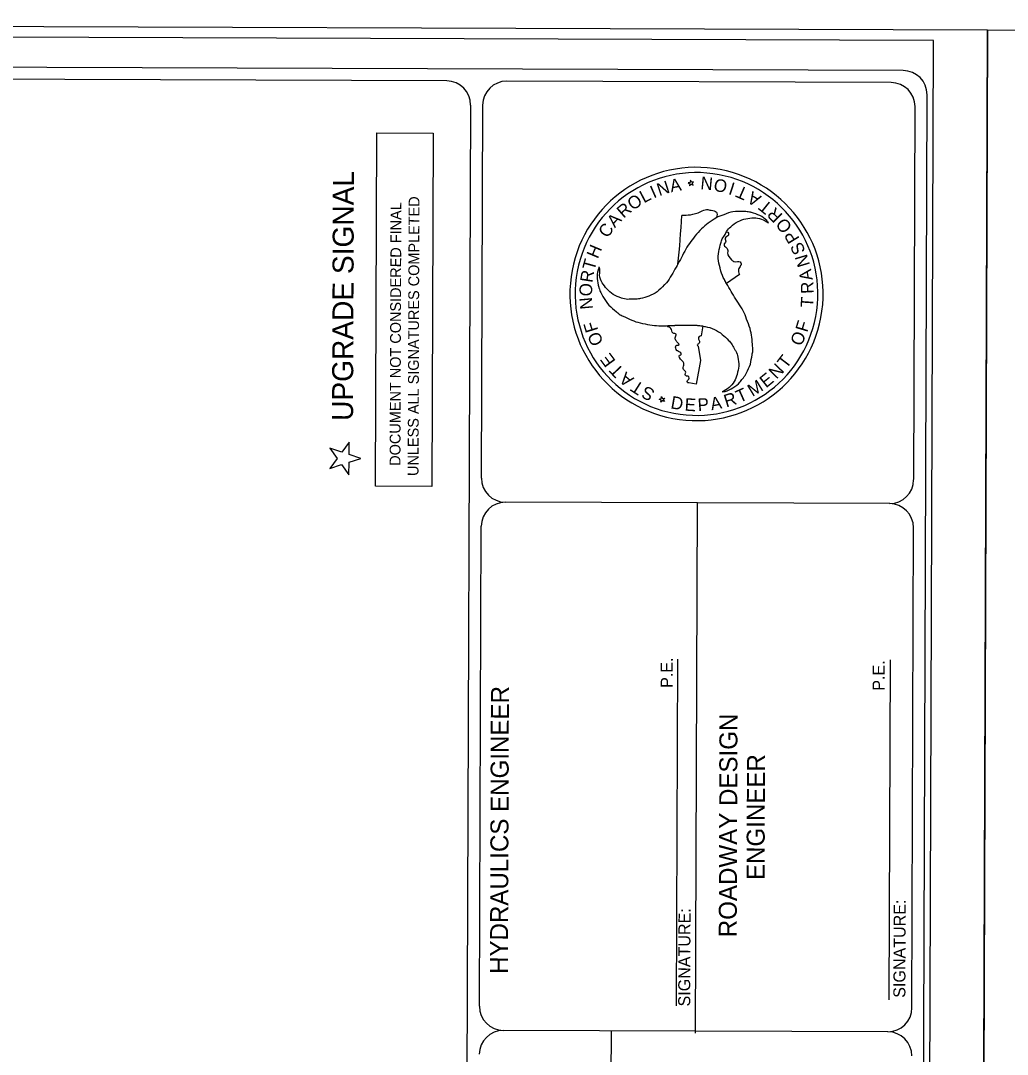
# Model space of a CAD drawing. Extents: x 2364794 to 2387902, y 795230 to 810426.
# Drawn here: x 2369718 to 2372593, y 807415 to 810426 of the extents above; entities that cross this region are included whole.
import ezdxf

# ---------------------------------------------------------------- set-up
doc = ezdxf.new("R2010")
doc.units = 0
for name, color, linetype in [('Auto Dimensioning', 7, 'Continuous'), ('Mis Object Lines', 7, 'Continuous'), ('Old_Level_21', 7, 'Continuous'), ('Old_Level_22', 7, 'Continuous'), ('Old_Level_8', 7, 'Continuous'), ('Plan Sheet CELL', 7, 'Continuous'), ('Sub End Bent Cap Lines CELL', 7, 'Continuous')]:
    doc.layers.add(name, color=color, linetype=linetype)

msp = doc.modelspace()

# ---------------------------------------------------------------- linework, layer by layer
at = {"layer": 'Auto Dimensioning'}
for p, q in [((2370751.7, 809070.1), (2370755.4, 810099.1)), ((2370755.5, 810099.1), (2370920, 810098.5)), ((2370919.9, 810098.5), (2370916.2, 809069.5)), ((2370916.2, 809069.5), (2370751.7, 809070.1))]:
    msp.add_line(p, q, dxfattribs=at)
at = {"layer": 'Mis Object Lines'}
for p, q in [((2370994.2, 800240.4), (2371029.3, 810180.3)), ((2371060.4, 809093.6), (2371064.3, 810180.2)), ((2371737.1, 809995.7), (2371737.1, 809995.7)), ((2371668.6, 809955.2), (2371662.4, 809953.8)), ((2371662.4, 809953.8), (2371668, 809951.1)), ((2371669.2, 809961.4), (2371668.6, 809955.2)), ((2371672.4, 809955.8), (2371669.2, 809961.4)), ((2371678.7, 809956.8), (2371672.4, 809955.8)), ((2371674.4, 809952.2), (2371678.7, 809956.8)), ((2371677.4, 809946.8), (2371674.4, 809952.2)), ((2371668, 809951.1), (2371667.2, 809944.8)), ((2371667.2, 809944.8), (2371671.6, 809949.5)), ((2371671.6, 809949.5), (2371677.4, 809946.8)), ((2371632.7, 809716.9), (2371632.7, 809716.9)), ((2371402.8, 809708.5), (2371403.5, 809707.7)), ((2371402.8, 809708.5), (2371403.5, 809707.7)), ((2371812.1, 809687.1), (2371774.7, 809661)), ((2371774.7, 809661), (2371774.7, 809661)), ((2371705.2, 809537), (2371700.9, 809508.1)), ((2371692.2, 809478.2), (2371698.4, 809436.8)), ((2371698.4, 809436.8), (2371686.4, 809367.8)), ((2371686.4, 809367.8), (2371664.5, 809371.6)), ((2371578.4, 809323.5), (2371584.6, 809324.8)), ((2371584, 809320.9), (2371578.4, 809323.5)), ((2371583.2, 809314.6), (2371584, 809320.9)), ((2371587.6, 809319.1), (2371583.2, 809314.6)), ((2371584.6, 809324.8), (2371585.4, 809331.1)), ((2371585.4, 809331.1), (2371588.5, 809325.4)), ((2371593.5, 809316.5), (2371587.6, 809319.1)), ((2371588.5, 809325.4), (2371594.8, 809326.5)), ((2371594.8, 809326.5), (2371590.3, 809321.9)), ((2371590.3, 809321.9), (2371593.5, 809316.5)), ((2372250.2, 809019.4), (2371130.2, 809023.4)), ((2371684.6, 807476.7), (2371690, 809021.4)), ((2371055, 807555.2), (2371059.9, 808953.6)), ((2371628.9, 807556.7), (2371632.5, 808566.4)), ((2372248.9, 807573.8), (2372252.5, 808564.3)), ((2372244.8, 807481), (2371124.8, 807485)), ((2371438.1, 807483.9), (2371430.5, 805348.9))]:
    msp.add_line(p, q, dxfattribs=at)
for points in [[(2372289.6, 810280.9), (2365079.8, 810306.4)], [(2370959.6, 810250.6), (2365114.6, 810271.2)], [(2372254.5, 810246), (2371134.5, 810250)], [(2372322.9, 799850.7), (2372359.5, 810210.6)], [(2372320.4, 809089.2), (2372324.3, 810175.8)], [(2372315, 807550.8), (2372319.9, 808949.2)]]:
    msp.add_lwpolyline(points, dxfattribs=at)
for centre, radius, start, end in [((2372289.1, 810210.9), 70, 359.7976, 89.7976), ((2370959, 810180.6), 70, 359.7976, 89.7976), ((2371134, 810180), 70, 89.7976, 179.7976), ((2372253.9, 810176), 70, 359.7976, 89.7976), ((2371687.2, 809630.1), 369, 82.2188, 262.2188), ((2371687.2, 809630.1), 353.6, 82.2188, 262.2188), ((2371687.2, 809630.1), 369, 262.2188, 82.2188), ((2371687.2, 809630.1), 353.6, 262.2188, 82.2188), ((2369700.2, 809942.6), 1945.6, 353.3363, 357.5423), ((2369700.2, 809942.6), 1945.6, 347.8972, 347.9968), ((2371130.4, 809093.4), 70, 179.7976, 269.7976), ((2372250, 809089.4), 70, 269.7976, 359.7976), ((2371129.9, 808953.4), 70, 89.7976, 179.7976), ((2372249.5, 808949.4), 70, 359.7976, 89.7976), ((2371124.7, 807555), 70, 179.7976, 269.7976), ((2372245, 807551), 70, 269.7976, 359.7976), ((2371124.2, 807415), 70, 89.7976, 179.7976), ((2372244.6, 807411), 70, 359.7976, 89.7976)]:
    msp.add_arc(centre, radius, start, end, dxfattribs=at)
for points in [[(2371896.9, 809837.4), (2371891.8, 809843.9), (2371871.8, 809858.3), (2371847.2, 809867.3), (2371844.8, 809868), (2371830.8, 809870.1), (2371814.2, 809870.5), (2371786.8, 809868), (2371760.6, 809858.7), (2371749.6, 809854.8), (2371738.4, 809847.7), (2371716, 809832.2), (2371697.2, 809815), (2371678.1, 809792.7), (2371662.8, 809772), (2371649.6, 809748.5), (2371637.1, 809724.8), (2371624.4, 809702.2), (2371610.8, 809678.6), (2371594.9, 809657.9), (2371593.2, 809656.3), (2371572.2, 809636.6), (2371548.1, 809624.2), (2371524, 809616.7), (2371511.5, 809614.9), (2371495.7, 809614.8), (2371486.6, 809614.4), (2371468.3, 809618.3), (2371444.5, 809629), (2371426.1, 809645.1), (2371412.3, 809663), (2371404.7, 809684.7), (2371403.5, 809707.7), (2371402.8, 809708.5)], [(2371644.1, 809859.2), (2371669.2, 809861), (2371699.7, 809869.9), (2371716.5, 809876), (2371730, 809873.9), (2371745.7, 809868.6), (2371745.2, 809852.8)], [(2371745.3, 809852.6), (2371738.4, 809847.7), (2371716, 809832.2), (2371697.2, 809815), (2371678.1, 809792.7), (2371662.8, 809772), (2371649.6, 809748.5), (2371637.1, 809724.8), (2371632.7, 809716.9)], [(2371762.4, 809345), (2371771, 809346.5), (2371793.3, 809356.6), (2371813.5, 809373.3), (2371814.9, 809375.2), (2371824.2, 809386.2), (2371832.5, 809400.2), (2371844.1, 809425.4), (2371849.2, 809452.5), (2371851.3, 809464), (2371850.7, 809477.7), (2371848.4, 809504.3), (2371843.1, 809529.1), (2371833.3, 809557.1), (2371823.2, 809580.6), (2371809.2, 809603.7), (2371794.8, 809626.4), (2371781.6, 809649), (2371768.4, 809672.3), (2371758.1, 809696.6), (2371757.5, 809699.2), (2371751.1, 809727), (2371752.3, 809753.8), (2371757.9, 809778.2), (2371762.4, 809790.7), (2371770.4, 809803.8), (2371774.6, 809812.2), (2371787, 809826.1), (2371808.1, 809841), (2371831.3, 809849.1), (2371853.9, 809852.1), (2371876.4, 809848), (2371896.9, 809837.4)], [(2371774.7, 809661), (2371768.4, 809672.3), (2371758.1, 809696.6), (2371757.5, 809699.2), (2371751.1, 809727), (2371752.3, 809753.8), (2371757.9, 809778.2), (2371762.4, 809790.7), (2371770.4, 809803.8), (2371774.4, 809811.6)], [(2371774.5, 809811.4), (2371780.4, 809807.2), (2371780.1, 809801.6), (2371771.1, 809793), (2371771.8, 809780.9), (2371768, 809775.9), (2371767.4, 809772.3), (2371776.9, 809762.3), (2371777.9, 809750.3), (2371789.3, 809729.4), (2371796.9, 809724.4), (2371814.7, 809723.4), (2371817.5, 809718.2), (2371815.8, 809712.7), (2371809.7, 809701.6), (2371812.1, 809687.1)], [(2371403.5, 809707.7), (2371400.2, 809699.8), (2371397.9, 809675.3), (2371402.4, 809649.6), (2371403.3, 809647.2), (2371408.1, 809634), (2371416.1, 809619.5), (2371432.1, 809597.1), (2371453.1, 809578.8), (2371462.2, 809571.4), (2371473.7, 809565.3), (2371498.4, 809553.7), (2371522.7, 809546), (2371551.6, 809540.4), (2371577.3, 809537.4), (2371604, 809538), (2371630.9, 809539), (2371657, 809539.3), (2371683.8, 809539.2), (2371710, 809535.8), (2371712.2, 809535.4), (2371739.4, 809526.9), (2371762.3, 809512.3), (2371780.8, 809495), (2371789, 809485.1), (2371796.9, 809471.6), (2371801.5, 809463.9), (2371807.7, 809446.1), (2371810.1, 809420.3), (2371805.4, 809396), (2371796.9, 809375.1), (2371782, 809357.7), (2371762.4, 809345)], [(2371664.5, 809371.6), (2371662.3, 809371.1), (2371660.4, 809375.1), (2371666.1, 809384.8), (2371662.3, 809390.6), (2371657.8, 809391), (2371654, 809395.7), (2371656.3, 809402.6), (2371649.1, 809410.1), (2371648.5, 809416.1), (2371650.2, 809428.5), (2371637.4, 809445.1), (2371637.4, 809451.4), (2371641.5, 809452.4), (2371642.8, 809456.1), (2371631.5, 809464), (2371630, 809465.9), (2371627, 809478), (2371629.6, 809480.7), (2371635.1, 809480.9), (2371636.4, 809482.4), (2371634.2, 809486.5), (2371628.4, 809492.5), (2371624.9, 809502.6), (2371627.6, 809513.1), (2371619.1, 809516.2), (2371612.4, 809529.9), (2371607.6, 809533.2), (2371602.5, 809534.6)], [(2371603.3, 809538), (2371604, 809538), (2371630.9, 809539), (2371657, 809539.3), (2371683.8, 809539.2), (2371705.2, 809536.9)], [(2371700.9, 809508.1), (2371695.2, 809506), (2371692.8, 809500.6), (2371695.8, 809492.5), (2371694.7, 809486.8), (2371689.3, 809481.1), (2371692.2, 809478.2)]]:
    msp.add_spline(points, degree=3, dxfattribs=at)
at = {"layer": 'Old_Level_21'}
for points in [[(2364835.2, 810426.2), (2364793.5, 798638.3), (2372493.4, 798611.1), (2372535.1, 810399)], [(2380193.4, 798583.9), (2380235, 810371.8), (2372535.1, 810399), (2372493.4, 798611.1)]]:
    msp.add_lwpolyline(points, close=True, dxfattribs=at)
at = {"layer": 'Old_Level_22'}
msp.add_lwpolyline([(2372336.7, 798702.6), (2372377.9, 810368.1), (2364992.2, 810394.2), (2364951, 798728.7)], close=True, dxfattribs=at)
at = {"layer": 'Old_Level_8'}
msp.add_lwpolyline([(2370674.6, 809162.5), (2370674.7, 809198.8), (2370653.3, 809169.5), (2370618.7, 809180.8), (2370640, 809151.3), (2370618.6, 809122), (2370653.1, 809133.1), (2370674.4, 809103.7), (2370674.5, 809140), (2370709.1, 809151.1), (2370674.6, 809162.5)], dxfattribs=at)
at = {"layer": 'Plan Sheet CELL'}
for p, q in [((2372493.4, 798611.1), (2372535.1, 810399)), ((2372535.1, 810399), (2372493.4, 798611.1))]:
    msp.add_line(p, q, dxfattribs=at)

# ---------------------------------------------------------------- texts
at = {"layer": 'Auto Dimensioning'}
for s, p in [('DOCUMENT NOT CONSIDERED FINAL', (2370824.4, 809129.6)), ('UNLESS ALL SIGNATURES COMPLETED', (2370877, 809099.9))]:
    msp.add_text(s, height=31.5, rotation=89.7976, dxfattribs=at).set_placement(p)
at = {"layer": 'Mis Object Lines'}
for s, height, rotation, p in [('N', 36.8, 18.1141, (2371578.7, 809915.1)), ('A', 36.8, 10.6821, (2371613.1, 809926.1)), ('N', 36.8, 174.4269, (2371736.5, 809968.8)), ('O', 36.7, 167.1789, (2371779.9, 809959.3)), ('I', 36.9, 162.0432, (2371802.4, 809952.2)), ('L', 36.7, 27.8035, (2371533.7, 809893.9)), ('I', 36.8, 23.8142, (2371562.2, 809908.1)), ('T', 36.7, 156.3933, (2371840.6, 809935.8)), ('A', 36.9, 149.3089, (2371878.3, 809913.9)), ('R', 36.8, 41.1568, (2371474.7, 809848.9)), ('O', 36.9, 34.0372, (2371501.2, 809872)), ('T', 36.7, 141.2219, (2371911.3, 809888.3)), ('R', 36.9, 135.1221, (2371940.5, 809860)), ('C', 36.7, 55.0178, (2371428, 809791)), ('A', 36.8, 47.5208, (2371449.2, 809821)), ('O', 36.9, 127.933, (2371968.1, 809825.1)), ('P', 36.8, 121.241, (2371988.8, 809791.5)), ('H', 36.7, 67.3601, (2371399.3, 809730.9)), ('S', 36.6, 114.0491, (2372005.6, 809754.5)), ('N', 36.7, 106.8387, (2372018.4, 809714.9)), ('T', 36.9, 74.4449, (2371389.4, 809696.3)), ('R', 36.8, 81.0945, (2371383.9, 809661.5)), ('A', 36.7, 99.807, (2372026.4, 809672.1)), ('O', 36.9, 87.7044, (2371382.4, 809622.6)), ('R', 36.8, 93.0539, (2372029.2, 809631.6)), ('T', 36.7, 86.0973, (2372026.8, 809590)), ('N', 36.8, 95.2025, (2371385.4, 809586.7)), ('F', 36.9, 107.2895, (2371401.1, 809524.7)), ('F', 36.8, 73.188, (2372009.7, 809516.7)), ('O', 36.8, 114.4363, (2371417, 809489.2)), ('O', 36.8, 66.0228, (2371992.2, 809475.8)), ('E', 36.7, 126.3757, (2371453.1, 809434.8)), ('T', 36.7, 52.7191, (2371948.9, 809410.3)), ('T', 36.7, 133.4913, (2371477.8, 809408.5)), ('N', 36.9, 45.8771, (2371920.3, 809380.2)), ('A', 36.9, 140.5465, (2371507.1, 809384.3)), ('M', 36.7, 31.4388, (2371850.2, 809329.8)), ('E', 36.7, 38.9056, (2371889.7, 809354.9)), ('T', 36.9, 147.5988, (2371537.2, 809364.7)), ('S', 36.8, 153.975, (2371568.7, 809349.2)), ('T', 36.8, 24.2038, (2371812.3, 809312.2)), ('D', 36.8, 350.0717, (2371610.1, 809297.2)), ('E', 36.6, 356.3596, (2371651.8, 809290.3)), ('P', 36.8, 3.892, (2371691.7, 809288.5)), ('A', 36.7, 10.4846, (2371731, 809291.2)), ('R', 36.8, 17.5532, (2371773.7, 809299.5)), ('P.E.', 35, 89.7976, (2371617.9, 808482.7)), ('P.E.', 35, 89.7976, (2372235.3, 808474.4)), (' HYDRAULICS ENGINEER', 52.5, 89.7976, (2371137.6, 807629.8)), ('ROADWAY DESIGN', 52.496, 89.7976, (2371804.4, 807756.3)), ('ENGINEER', 52.5, 89.7976, (2371885.5, 807922.9)), ('SIGNATURE:', 35, 89.7976, (2372295.8, 807579.9)), ('SIGNATURE:', 35, 89.7976, (2371668.8, 807554.6))]:
    msp.add_text(s, height=height, rotation=rotation, dxfattribs=at).set_placement(p)
at = {"layer": 'Sub End Bent Cap Lines CELL'}
msp.add_text('UPGRADE SIGNAL', height=61.251, rotation=89.7976, dxfattribs=at).set_placement((2370686.3, 809260.1))

doc.saveas('drawing.dxf')
